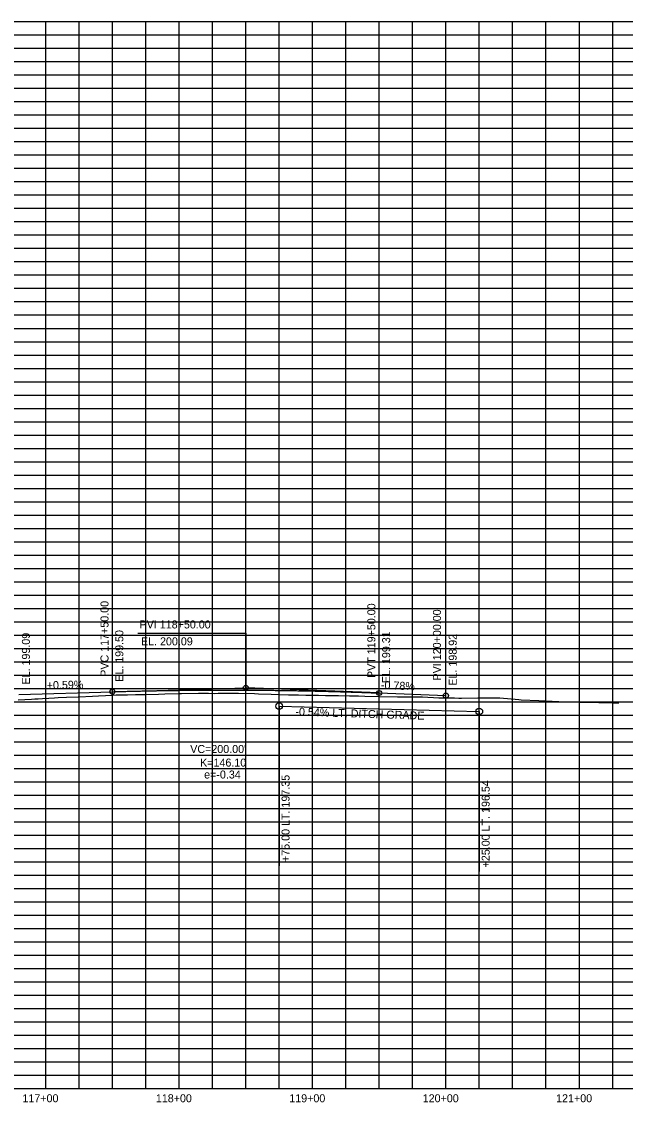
# Model space of a CAD drawing. Extents: x 1384498 to 1391279, y 1965973 to 1976560.
# Drawn here: x 1390131 to 1390583, y 1975299 to 1976110 of the extents above; entities that cross this region are included whole.
import ezdxf

# ---------------------------------------------------------------- set-up
doc = ezdxf.new("R2010")
doc.units = 0
for name, color, linetype in [('Default', 7, 'Continuous'), ('R_Axis_Annotation', 7, 'Continuous'), ('R_Exist Surface', 7, 'Continuous'), ('R_Grid', 7, 'Continuous'), ('R_Grid_Minor', 7, 'Continuous'), ('R_Vert Alg', 7, 'Continuous'), ('R_Vert Alg Annot', 7, 'Continuous')]:
    doc.layers.add(name, color=color, linetype=linetype)

msp = doc.modelspace()

# ---------------------------------------------------------------- linework, layer by layer
at = {"layer": 'Default'}
msp.add_line((1388248.79, 1975309.84), (1390648.79, 1975309.84), dxfattribs=at)
at = {"layer": 'R_Exist Surface'}
msp.add_lwpolyline([(1390128.08, 1975601.16), (1390138.24, 1975601.8), (1390140.76, 1975601.94), (1390143.12, 1975602.08), (1390146.39, 1975602.29), (1390151.16, 1975602.59), (1390155.37, 1975602.85), (1390158.24, 1975603.02), (1390164.35, 1975603.22), (1390173.26, 1975603.57), (1390173.35, 1975603.57), (1390173.57, 1975603.59), (1390183.93, 1975604.12), (1390188.32, 1975604.35), (1390199, 1975604.78), (1390201.73, 1975604.89), (1390202.35, 1975604.92), (1390202.62, 1975604.93), (1390203.32, 1975604.95), (1390203.9, 1975604.96), (1390204.07, 1975604.96), (1390204.38, 1975604.97), (1390205.16, 1975604.98), (1390210.15, 1975605.05), (1390216.13, 1975605.14), (1390218.33, 1975605.19), (1390223.1, 1975605.29), (1390233.34, 1975605.52), (1390238.05, 1975605.69), (1390248.34, 1975606.03), (1390248.95, 1975606.03), (1390250.55, 1975606.06), (1390263.35, 1975606.23), (1390270.84, 1975606.18), (1390275.32, 1975606.13), (1390278.17, 1975606.15), (1390281.66, 1975606.19), (1390291.06, 1975606.28), (1390292.59, 1975606.29), (1390293.36, 1975606.3), (1390305.2, 1975605.93), (1390308.36, 1975605.84), (1390317.78, 1975605.52), (1390323.36, 1975605.31), (1390330.69, 1975605.1), (1390338.36, 1975604.92), (1390343.87, 1975604.82), (1390353.36, 1975604.64), (1390358.45, 1975604.56), (1390368.35, 1975604.41), (1390376.6, 1975604.34), (1390383.35, 1975604.34), (1390388.13, 1975604.11), (1390398.35, 1975603.75), (1390412.51, 1975603.4), (1390413.36, 1975603.39), (1390416.98, 1975603.42), (1390426.5, 1975603.51), (1390427.34, 1975603.52), (1390427.66, 1975603.53), (1390427.83, 1975603.54), (1390427.93, 1975603.54), (1390428.36, 1975603.54), (1390429.59, 1975603.5), (1390431.13, 1975603.43), (1390443.36, 1975602.87), (1390455.24, 1975602.67), (1390458.35, 1975602.6), (1390460.54, 1975602.61), (1390472.79, 1975602.75), (1390473.27, 1975602.75), (1390473.35, 1975602.75), (1390475.26, 1975602.75), (1390487.71, 1975602.73), (1390488.36, 1975602.74), (1390489.09, 1975602.67), (1390503.36, 1975601.43), (1390505.13, 1975601.35), (1390518.36, 1975600.81), (1390528.43, 1975600.32), (1390533.36, 1975600.05), (1390542.91, 1975599.71), (1390548.35, 1975599.54), (1390553.61, 1975599.39), (1390563.36, 1975599.16), (1390573.62, 1975599.05), (1390578.36, 1975599.01)], dxfattribs=at)
at = {"layer": 'R_Grid'}
for p, q in [((1388248.79, 1976109.84), (1391048.79, 1976109.84)), ((1388248.79, 1976109.84), (1391048.79, 1976109.84)), ((1390148.79, 1975309.84), (1390148.79, 1976109.84)), ((1390248.79, 1975309.84), (1390248.79, 1976109.84)), ((1390348.79, 1975309.84), (1390348.79, 1976109.84)), ((1390448.79, 1975309.84), (1390448.79, 1976109.84)), ((1390548.79, 1975309.84), (1390548.79, 1976109.84)), ((1388248.79, 1976059.84), (1391048.79, 1976059.84)), ((1388248.79, 1976009.84), (1391048.79, 1976009.84)), ((1388248.79, 1975959.84), (1391048.79, 1975959.84)), ((1388248.79, 1975909.84), (1391048.79, 1975909.84)), ((1388248.79, 1975859.84), (1391048.79, 1975859.84)), ((1388248.79, 1975809.84), (1391048.79, 1975809.84)), ((1388248.79, 1975759.84), (1391048.79, 1975759.84)), ((1388248.79, 1975709.84), (1391048.79, 1975709.84)), ((1388248.79, 1975659.84), (1391048.79, 1975659.84)), ((1388248.79, 1975609.84), (1391048.79, 1975609.84)), ((1388248.79, 1975559.84), (1391048.79, 1975559.84)), ((1388248.79, 1975509.84), (1391048.79, 1975509.84)), ((1388248.79, 1975459.84), (1391048.79, 1975459.84)), ((1388248.79, 1975409.84), (1391048.79, 1975409.84)), ((1388248.79, 1975359.84), (1391048.79, 1975359.84)), ((1388248.79, 1975309.84), (1391048.79, 1975309.84))]:
    msp.add_line(p, q, dxfattribs=at)
at = {"layer": 'R_Grid_Minor'}
for p, q in [((1390173.79, 1975309.84), (1390173.79, 1976109.84)), ((1390198.79, 1975309.84), (1390198.79, 1976109.84)), ((1390223.79, 1975309.84), (1390223.79, 1976109.84)), ((1390273.79, 1975309.84), (1390273.79, 1976109.84)), ((1390298.79, 1975309.84), (1390298.79, 1976109.84)), ((1390323.79, 1975309.84), (1390323.79, 1976109.84)), ((1390373.79, 1975309.84), (1390373.79, 1976109.84)), ((1390398.79, 1975309.84), (1390398.79, 1976109.84)), ((1390423.79, 1975309.84), (1390423.79, 1976109.84)), ((1390473.79, 1975309.84), (1390473.79, 1976109.84)), ((1390498.79, 1975309.84), (1390498.79, 1976109.84)), ((1390523.79, 1975309.84), (1390523.79, 1976109.84)), ((1390573.79, 1975309.84), (1390573.79, 1976109.84)), ((1388248.79, 1976099.84), (1391048.79, 1976099.84)), ((1388248.79, 1976089.84), (1391048.79, 1976089.84)), ((1388248.79, 1976079.84), (1391048.79, 1976079.84)), ((1388248.79, 1976069.84), (1391048.79, 1976069.84)), ((1388248.79, 1976049.84), (1391048.79, 1976049.84)), ((1388248.79, 1976039.84), (1391048.79, 1976039.84)), ((1388248.79, 1976029.84), (1391048.79, 1976029.84)), ((1388248.79, 1976019.84), (1391048.79, 1976019.84)), ((1388248.79, 1975999.84), (1391048.79, 1975999.84)), ((1388248.79, 1975989.84), (1391048.79, 1975989.84)), ((1388248.79, 1975979.84), (1391048.79, 1975979.84)), ((1388248.79, 1975969.84), (1391048.79, 1975969.84)), ((1388248.79, 1975949.84), (1391048.79, 1975949.84)), ((1388248.79, 1975939.84), (1391048.79, 1975939.84)), ((1388248.79, 1975929.84), (1391048.79, 1975929.84)), ((1388248.79, 1975919.84), (1391048.79, 1975919.84)), ((1388248.79, 1975899.84), (1391048.79, 1975899.84)), ((1388248.79, 1975889.84), (1391048.79, 1975889.84)), ((1388248.79, 1975879.84), (1391048.79, 1975879.84)), ((1388248.79, 1975869.84), (1391048.79, 1975869.84)), ((1388248.79, 1975849.84), (1391048.79, 1975849.84)), ((1388248.79, 1975839.84), (1391048.79, 1975839.84)), ((1388248.79, 1975829.84), (1391048.79, 1975829.84)), ((1388248.79, 1975819.84), (1391048.79, 1975819.84)), ((1388248.79, 1975799.84), (1391048.79, 1975799.84)), ((1388248.79, 1975789.84), (1391048.79, 1975789.84)), ((1388248.79, 1975779.84), (1391048.79, 1975779.84)), ((1388248.79, 1975769.84), (1391048.79, 1975769.84)), ((1388248.79, 1975749.84), (1391048.79, 1975749.84)), ((1388248.79, 1975739.84), (1391048.79, 1975739.84)), ((1388248.79, 1975729.84), (1391048.79, 1975729.84)), ((1388248.79, 1975719.84), (1391048.79, 1975719.84)), ((1388248.79, 1975699.84), (1391048.79, 1975699.84)), ((1388248.79, 1975689.84), (1391048.79, 1975689.84)), ((1388248.79, 1975679.84), (1391048.79, 1975679.84)), ((1388248.79, 1975669.84), (1391048.79, 1975669.84)), ((1388248.79, 1975649.84), (1391048.79, 1975649.84)), ((1388248.79, 1975639.84), (1391048.79, 1975639.84)), ((1388248.79, 1975629.84), (1391048.79, 1975629.84)), ((1388248.79, 1975619.84), (1391048.79, 1975619.84)), ((1388248.79, 1975599.84), (1391048.79, 1975599.84)), ((1388248.79, 1975589.84), (1391048.79, 1975589.84)), ((1388248.79, 1975579.84), (1391048.79, 1975579.84)), ((1388248.79, 1975569.84), (1391048.79, 1975569.84)), ((1388248.79, 1975549.84), (1391048.79, 1975549.84)), ((1388248.79, 1975539.84), (1391048.79, 1975539.84)), ((1388248.79, 1975529.84), (1391048.79, 1975529.84)), ((1388248.79, 1975519.84), (1391048.79, 1975519.84)), ((1388248.79, 1975499.84), (1391048.79, 1975499.84)), ((1388248.79, 1975489.84), (1391048.79, 1975489.84)), ((1388248.79, 1975479.84), (1391048.79, 1975479.84)), ((1388248.79, 1975469.84), (1391048.79, 1975469.84)), ((1388248.79, 1975449.84), (1391048.79, 1975449.84)), ((1388248.79, 1975439.84), (1391048.79, 1975439.84)), ((1388248.79, 1975429.84), (1391048.79, 1975429.84)), ((1388248.79, 1975419.84), (1391048.79, 1975419.84)), ((1388248.79, 1975399.84), (1391048.79, 1975399.84)), ((1388248.79, 1975389.84), (1391048.79, 1975389.84)), ((1388248.79, 1975379.84), (1391048.79, 1975379.84)), ((1388248.79, 1975369.84), (1391048.79, 1975369.84)), ((1388248.79, 1975349.84), (1391048.79, 1975349.84)), ((1388248.79, 1975339.84), (1391048.79, 1975339.84)), ((1388248.79, 1975329.84), (1391048.79, 1975329.84)), ((1388248.79, 1975319.84), (1391048.79, 1975319.84))]:
    msp.add_line(p, q, dxfattribs=at)
at = {"layer": 'R_Vert Alg'}
for p, q in [((1390128.79, 1975605.28), (1390198.79, 1975607.34)), ((1390398.79, 1975606.39), (1390448.79, 1975604.44)), ((1390323.79, 1975596.59), (1390473.79, 1975592.54))]:
    msp.add_line(p, q, dxfattribs=at)
msp.add_spline([(1390198.79, 1975607.34), (1390202.79, 1975607.46), (1390206.79, 1975607.57), (1390210.79, 1975607.67), (1390214.79, 1975607.77), (1390218.79, 1975607.86), (1390222.79, 1975607.95), (1390226.79, 1975608.03), (1390230.79, 1975608.11), (1390234.79, 1975608.18), (1390238.79, 1975608.25), (1390242.79, 1975608.31), (1390246.79, 1975608.36), (1390250.79, 1975608.41), (1390254.79, 1975608.46), (1390258.79, 1975608.49), (1390262.79, 1975608.53), (1390266.79, 1975608.56), (1390270.79, 1975608.58), (1390274.79, 1975608.59), (1390278.79, 1975608.6), (1390282.79, 1975608.61), (1390286.79, 1975608.61), (1390290.79, 1975608.6), (1390294.79, 1975608.59), (1390298.79, 1975608.58), (1390302.79, 1975608.56), (1390306.79, 1975608.53), (1390310.79, 1975608.5), (1390314.79, 1975608.46), (1390318.79, 1975608.41), (1390322.79, 1975608.36), (1390326.79, 1975608.31), (1390330.79, 1975608.25), (1390334.79, 1975608.18), (1390338.79, 1975608.11), (1390342.79, 1975608.04), (1390346.79, 1975607.95), (1390350.79, 1975607.87), (1390354.79, 1975607.77), (1390358.79, 1975607.67), (1390362.79, 1975607.57), (1390366.79, 1975607.46), (1390370.79, 1975607.35), (1390374.79, 1975607.23), (1390378.79, 1975607.1), (1390382.79, 1975606.97), (1390386.79, 1975606.83), (1390390.79, 1975606.69), (1390394.79, 1975606.54), (1390398.79, 1975606.39)], degree=3, dxfattribs=at)
at = {"layer": 'R_Vert Alg Annot'}
for p, q in [((1390198.79, 1975617.34), (1390198.79, 1975701.34)), ((1390398.79, 1975616.39), (1390398.79, 1975700.39)), ((1390448.79, 1975613.61), (1390448.79, 1975697.61)), ((1390217.96, 1975651.3), (1390298.79, 1975651.3)), ((1390298.79, 1975651.3), (1390298.79, 1975610.29)), ((1390198.79, 1975607.34), (1390198.79, 1975617.34)), ((1390398.79, 1975606.39), (1390398.79, 1975616.39)), ((1390198.79, 1975607.34), (1390298.79, 1975610.29)), ((1390398.79, 1975606.39), (1390298.79, 1975610.29)), ((1390448.79, 1975604.44), (1390448.79, 1975613.61)), ((1390323.79, 1975596.59), (1390323.79, 1975476.67)), ((1390473.79, 1975592.54), (1390473.79, 1975472.62))]:
    msp.add_line(p, q, dxfattribs=at)
for centre, radius in [((1390198.79, 1975607.34), 1.85), ((1390298.79, 1975610.29), 1.85), ((1390398.79, 1975606.39), 1.85), ((1390448.79, 1975604.44), 1.85), ((1390323.79, 1975596.59), 2.5), ((1390473.79, 1975592.54), 2.5)]:
    msp.add_circle(centre, radius, dxfattribs=at)

# ---------------------------------------------------------------- texts
at = {"layer": 'R_Axis_Annotation'}
for s, p in [('117+00', (1390131.38, 1975299.49)), ('118+00', (1390231.38, 1975299.49)), ('119+00', (1390331.38, 1975299.49)), ('120+00', (1390431.38, 1975299.49)), ('121+00', (1390531.38, 1975299.49))]:
    msp.add_text(s, height=6, dxfattribs=at).set_placement(p)
at = {"layer": 'R_Vert Alg Annot'}
for s, rotation, p in [('PVC 117+50.00', 90, (1390195.89, 1975618.57)), ('PVT 119+50.00', 90, (1390395.89, 1975617.61)), ('PVI 120+00.00', 90, (1390445.05, 1975615.78)), (' EL. 199.09', 90, (1390136.99, 1975610.49)), (' EL. 199.50', 90, (1390206.99, 1975612.55)), (' EL. 199.31', 90, (1390406.99, 1975611.59)), (' EL. 198.92', 90, (1390456.88, 1975609.67)), ('+0.59%', 1.19692, (1390149.65, 1975609.19)), ('-0.78%', 357.30504, (1390399.97, 1975609.53)), ('-0.54% LT. DITCH GRADE', 358.14235, (1390335.89, 1975589.48)), ('+75.00 LT. 197.35', 90, (1390331.57, 1975479.67)), ('+25.00 LT. 196.54', 90, (1390481.57, 1975475.62))]:
    msp.add_text(s, height=6, rotation=rotation, dxfattribs=at).set_placement(p)
for s, p in [('PVI 118+50.00', (1390219.16, 1975654.8)), ('EL. 200.09', (1390220.23, 1975642.11)), ("VC=200.00'", (1390257.13, 1975561.39)), ('K=146.10', (1390264.55, 1975551.2)), ('e=-0.34', (1390267.56, 1975542.26))]:
    msp.add_text(s, height=6, dxfattribs=at).set_placement(p)

doc.saveas('drawing.dxf')
